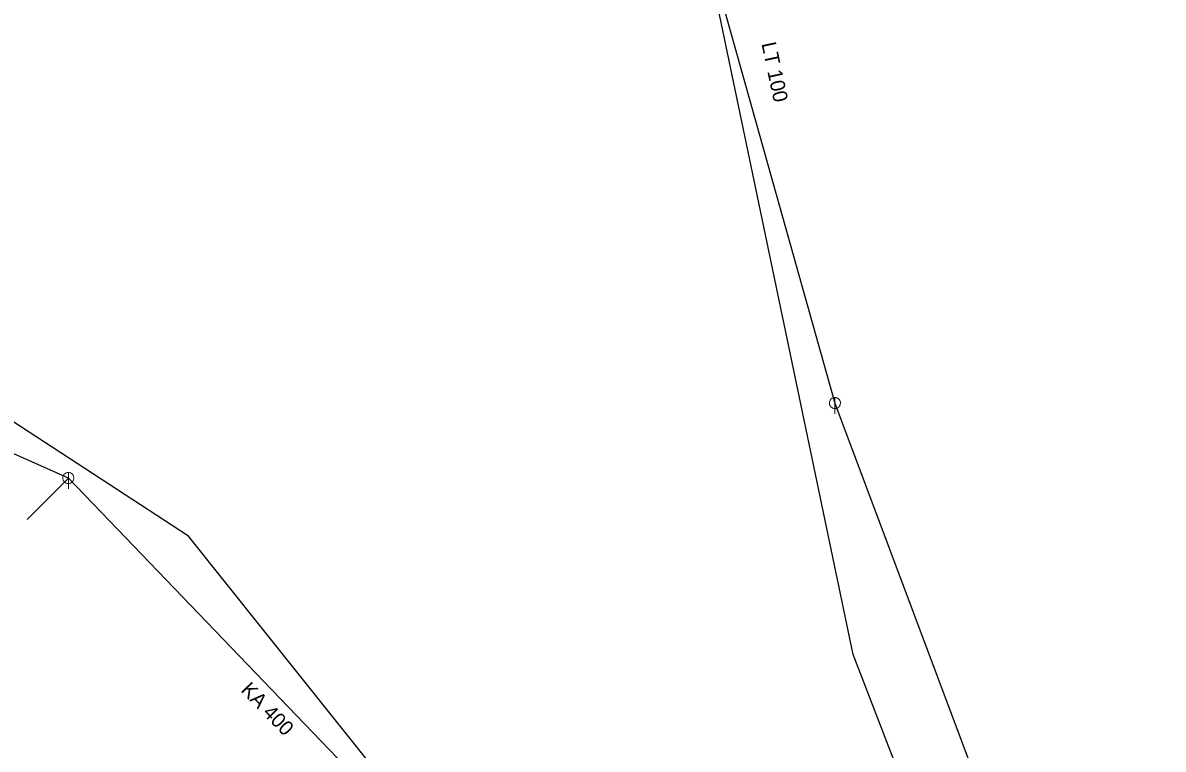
# Model space of a CAD drawing. Extents: x -687468 to -685917, y -974192 to -973456.
# Drawn here: x -686435.6 to -686383.6, y -973735.1 to -973702 of the extents above; entities that cross this region are included whole.
import ezdxf
from ezdxf.enums import TextEntityAlignment as Align

# ---------------------------------------------------------------- set-up
doc = ezdxf.new("R2010")
doc.units = 0
doc.header["$LTSCALE"] = 0.27
for name, color, linetype, lineweight in [('1', 7, 'Continuous', 13), ('11', 7, 'Continuous', 13), ('14', 7, 'Continuous', 25), ('17', 7, 'Continuous', 25), ('22', 7, 'Continuous', 13)]:
    doc.layers.add(name, color=color, linetype=linetype, lineweight=lineweight)

msp = doc.modelspace()

# ---------------------------------------------------------------- linework, layer by layer
at = {"layer": '11'}
msp.add_line((-686435.423, -973724.656), (-686433.55, -973722.77), dxfattribs=at)
at = {"layer": '14'}
for p, q in [((-686398.605, -973719.353), (-686383.64, -973759.25)), ((-686411.96, -973745.23), (-686433.55, -973722.77))]:
    msp.add_line(p, q, dxfattribs=at)
for points in [[(-686402, -973678.71), (-686408.76, -973683.21), (-686398.605, -973719.354)], [(-686433.55, -973722.77), (-686436.316, -973721.542), (-686443.219, -973718.48)]]:
    msp.add_lwpolyline(points, dxfattribs=at)
at = {"layer": '17'}
for points in [[(-686390.37, -973750.001), (-686397.766, -973730.818), (-686407.937, -973682.144)], [(-686390.795, -973750.272), (-686404.794, -973749.853), (-686409.23, -973746.732), (-686417.835, -973738.241), (-686428.076, -973725.42), (-686438.98, -973718.313), (-686458.311, -973716.826), (-686472.603, -973718.727), (-686490.318, -973720.708), (-686506.346, -973717.746)]]:
    msp.add_lwpolyline(points, dxfattribs=at)
at = {"layer": '22'}
for p, q in [((-686398.604, -973719.102), (-686398.605, -973719.846)), ((-686433.549, -973722.518), (-686433.55, -973723.262))]:
    msp.add_line(p, q, dxfattribs=at)
for points in [[(-686398.353, -973719.354), (-686398.354, -973719.328), (-686398.358, -973719.302), (-686398.364, -973719.276), (-686398.374, -973719.252), (-686398.386, -973719.228), (-686398.4, -973719.206), (-686398.417, -973719.185), (-686398.435, -973719.167), (-686398.456, -973719.15), (-686398.478, -973719.136), (-686398.502, -973719.124), (-686398.526, -973719.114), (-686398.552, -973719.108), (-686398.578, -973719.104), (-686398.604, -973719.102), (-686398.63, -973719.103), (-686398.656, -973719.107), (-686398.682, -973719.113), (-686398.707, -973719.123), (-686398.73, -973719.135), (-686398.752, -973719.149), (-686398.773, -973719.166), (-686398.791, -973719.184), (-686398.808, -973719.205), (-686398.822, -973719.227), (-686398.834, -973719.251), (-686398.844, -973719.275), (-686398.851, -973719.301), (-686398.855, -973719.327), (-686398.857, -973719.353), (-686398.856, -973719.379), (-686398.852, -973719.405), (-686398.845, -973719.431), (-686398.835, -973719.456), (-686398.823, -973719.479), (-686398.809, -973719.501), (-686398.792, -973719.522), (-686398.774, -973719.54), (-686398.753, -973719.557), (-686398.731, -973719.571), (-686398.708, -973719.583), (-686398.683, -973719.593), (-686398.657, -973719.6), (-686398.631, -973719.604), (-686398.605, -973719.606), (-686398.579, -973719.605), (-686398.553, -973719.601), (-686398.527, -973719.594), (-686398.503, -973719.584), (-686398.479, -973719.572), (-686398.457, -973719.558), (-686398.436, -973719.541), (-686398.418, -973719.523), (-686398.401, -973719.502), (-686398.387, -973719.48), (-686398.375, -973719.457), (-686398.365, -973719.432), (-686398.359, -973719.406), (-686398.355, -973719.38)], [(-686433.298, -973722.77), (-686433.299, -973722.744), (-686433.303, -973722.718), (-686433.309, -973722.692), (-686433.319, -973722.668), (-686433.331, -973722.644), (-686433.345, -973722.622), (-686433.362, -973722.601), (-686433.38, -973722.583), (-686433.401, -973722.566), (-686433.423, -973722.552), (-686433.447, -973722.54), (-686433.471, -973722.53), (-686433.497, -973722.524), (-686433.523, -973722.52), (-686433.549, -973722.518), (-686433.575, -973722.519), (-686433.601, -973722.523), (-686433.627, -973722.529), (-686433.652, -973722.539), (-686433.675, -973722.551), (-686433.697, -973722.565), (-686433.718, -973722.582), (-686433.736, -973722.6), (-686433.753, -973722.621), (-686433.767, -973722.643), (-686433.779, -973722.667), (-686433.789, -973722.691), (-686433.796, -973722.717), (-686433.8, -973722.743), (-686433.802, -973722.769), (-686433.801, -973722.795), (-686433.797, -973722.821), (-686433.79, -973722.847), (-686433.78, -973722.872), (-686433.768, -973722.895), (-686433.754, -973722.917), (-686433.737, -973722.938), (-686433.719, -973722.956), (-686433.698, -973722.973), (-686433.676, -973722.987), (-686433.653, -973722.999), (-686433.628, -973723.009), (-686433.602, -973723.016), (-686433.576, -973723.02), (-686433.55, -973723.022), (-686433.524, -973723.021), (-686433.498, -973723.017), (-686433.472, -973723.01), (-686433.448, -973723), (-686433.424, -973722.988), (-686433.402, -973722.974), (-686433.381, -973722.957), (-686433.363, -973722.939), (-686433.346, -973722.918), (-686433.332, -973722.896), (-686433.32, -973722.873), (-686433.31, -973722.848), (-686433.304, -973722.822), (-686433.3, -973722.796)]]:
    msp.add_lwpolyline(points, close=True, dxfattribs=at)

# ---------------------------------------------------------------- texts
at = {"layer": '1'}
for s, rotation, p in [('LT 100', 282, (-686401.669, -973704.329)), ('KA 400', 314, (-686424.708, -973733.521))]:
    msp.add_text(s, height=0.6667, rotation=rotation, dxfattribs=at).set_placement(p, align=Align.CENTER)

doc.saveas('drawing.dxf')
